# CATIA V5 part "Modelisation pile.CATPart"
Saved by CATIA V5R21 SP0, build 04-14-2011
Part number: Modelisation pile
Bounding box of the stored display mesh (mm): x 0 to 78.3, y 0 to 62, z 0 to 30
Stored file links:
  C:\Users\2027.DESARCY-LEMIE30\Desktop\Assemblage26.05\Modelisation pile.CATPart
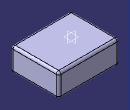
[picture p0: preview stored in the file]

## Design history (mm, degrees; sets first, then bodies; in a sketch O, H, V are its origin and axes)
Body1 (main body)
  Sketch1 on xy-plane, origin (0, 0, 0), H (1, 0, 0), V (0, 1, 0)
    line L1 (0, 62) -> (78.3, 62)
    line L2 (78.3, 62) -> (78.3, 0)
    line L3 (78.3, 0) -> (0, 0)
    line L4 (0, 0) -> (0, 62)
    point P3 (78.3, 0)
    point P4 (0, 0)
    length L2 = 62
    length L3 = 78.3
    horizontal: L1 H, L3 H
    vertical: L2 V, L4 V
    coincidence: P3 H, P4 O
  Pad1: profile Sketch1, direction (0, 0, 1), length 30
  Fillet1: radius 3, on edge [face of Pad1 from Sketch1.L4 | end face of Pad1]; edge [face of Pad1 from Sketch1.L1 | end face of Pad1]; edge [face of Pad1 from Sketch1.L3 | end face of Pad1]; edge [face of Pad1 from Sketch1.L2 | end face of Pad1]
  Fillet2: radius 3, on edge [start face of Pad1 | face of Pad1 from Sketch1.L1]; edge [start face of Pad1 | face of Pad1 from Sketch1.L4]; edge [start face of Pad1 | face of Pad1 from Sketch1.L3]; edge [start face of Pad1 | face of Pad1 from Sketch1.L2]
  Fillet3: radius 3, on edge [face of Pad1 from Sketch1.L3 | face of Pad1 from Sketch1.L4]; edge [face of Pad1 from Sketch1.L1 | face of Pad1 from Sketch1.L2]; edge [face of Pad1 from Sketch1.L2 | face of Pad1 from Sketch1.L3]; edge [face of Pad1 from Sketch1.L4 | face of Pad1 from Sketch1.L1]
